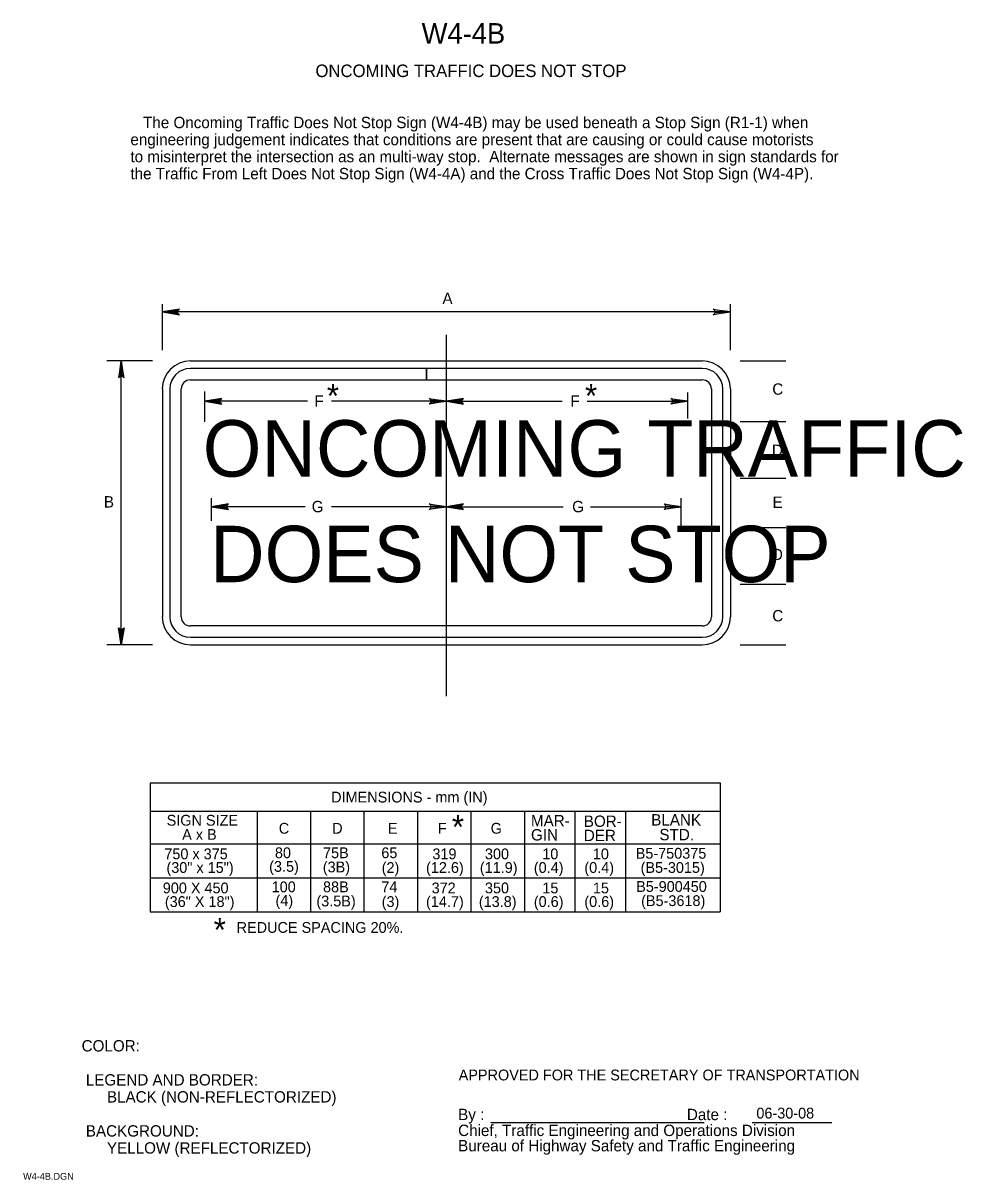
# Model space of a CAD drawing. Extents: x 0.013 to 0.219, y 0.004 to 0.259.
import ezdxf

# ---------------------------------------------------------------- set-up
doc = ezdxf.new("R2010")
doc.units = 0
for name, color, linetype in [('1', 7, 'Continuous'), ('2', 7, 'Continuous'), ('3', 7, 'Continuous')]:
    doc.layers.add(name, color=color, linetype=linetype)

# ---------------------------------------------------------------- blocks, each defined once
blk = doc.blocks.new('RARROW')
at = {"layer": '3'}
for p, q in [((-2.156, 0.285), (-2.2665, 0.384625)), ((-2.2665, 0.384625), (0, 0)), ((0, 0), (-2.2665, -0.379125)), ((-2.156, 0.285), (-2.075625, 0.12075)), ((0, 0), (-2.156, 0.285)), ((-2.14975, -0.2705), (0, 0)), ((-2.075625, 0.12075), (0, 0)), ((0, 0), (-2.074, -0.108)), ((-2.2665, -0.379125), (-2.14975, -0.2705)), ((-2.074, -0.108), (-2.14975, -0.2705))]:
    blk.add_line(p, q, dxfattribs=at)

msp = doc.modelspace()

# ---------------------------------------------------------------- linework, layer by layer
at = {"layer": '1'}
for p, q in [((0.10565, 0.11086), (0.10565, 0.19039)), ((0.0341, 0.12213), (0.0341, 0.18463)), ((0.10127, 0.18297), (0.04931, 0.18297)), ((0.10127, 0.18047), (0.10127, 0.18297)), ((0.16198, 0.18297), (0.10127, 0.18297)), ((0.10127, 0.18297), (0.10127, 0.18047)), ((0.04481, 0.17847), (0.04481, 0.1283)), ((0.04731, 0.1283), (0.04731, 0.17847)), ((0.04931, 0.18047), (0.10127, 0.18047)), ((0.10127, 0.18047), (0.16198, 0.18047)), ((0.16398, 0.17847), (0.16398, 0.1283)), ((0.16648, 0.1283), (0.16648, 0.17847)), ((0.05248, 0.17123), (0.05248, 0.17793)), ((0.10565, 0.17326), (0.10565, 0.17793)), ((0.15881, 0.17194), (0.15881, 0.17769)), ((0.05398, 0.14943), (0.05398, 0.15446)), ((0.10565, 0.15098), (0.10565, 0.1541)), ((0.15731, 0.14823), (0.15731, 0.15446)), ((0.16198, 0.1263), (0.04931, 0.1263)), ((0.04931, 0.1238), (0.16198, 0.1238)), ((0.11544, 0.01695), (0.16242, 0.01695)), ((0.17295, 0.01695), (0.1905, 0.01695))]:
    msp.add_line(p, q, dxfattribs=at)
for centre, radius, start, end in [((0.04931, 0.17847), 0.00617, 90, 180), ((0.16198, 0.17847), 0.00617, 360, 90), ((0.04931, 0.17847), 0.0045, 90, 180), ((0.16198, 0.17847), 0.0045, 0, 90), ((0.04931, 0.17847), 0.002, 90, 180), ((0.16198, 0.17847), 0.002, 0, 90), ((0.04931, 0.1283), 0.00617, 180, 270), ((0.04931, 0.1283), 0.0045, 180, 270), ((0.04931, 0.1283), 0.002, 180, 270), ((0.16198, 0.1283), 0.00617, 270, 0), ((0.16198, 0.1283), 0.0045, 270, 0), ((0.16198, 0.1283), 0.002, 270, 0)]:
    msp.add_arc(centre, radius, start, end, dxfattribs=at)
at = {"layer": '3'}
for p, q in [((0.04315, 0.18704), (0.04315, 0.1971)), ((0.16815, 0.18704), (0.16815, 0.1971)), ((0.16815, 0.19541), (0.04315, 0.19541)), ((0.04098, 0.18463), (0.03092, 0.18463)), ((0.04931, 0.18463), (0.16198, 0.18463)), ((0.17031, 0.18463), (0.18037, 0.18463)), ((0.04315, 0.17847), (0.04315, 0.1283)), ((0.16815, 0.17847), (0.16815, 0.1283)), ((0.07509, 0.17577), (0.05248, 0.17577)), ((0.10565, 0.17577), (0.08036, 0.17577)), ((0.10565, 0.17577), (0.13114, 0.17577)), ((0.13665, 0.17577), (0.15881, 0.17577)), ((0.17031, 0.1713), (0.18037, 0.1713)), ((0.17031, 0.1588), (0.18037, 0.1588)), ((0.07461, 0.15254), (0.05398, 0.15254)), ((0.10565, 0.15254), (0.08036, 0.15254)), ((0.10565, 0.15254), (0.13138, 0.15254)), ((0.13737, 0.15254), (0.15731, 0.15254)), ((0.17031, 0.14796), (0.18037, 0.14796)), ((0.17031, 0.13546), (0.18037, 0.13546)), ((0.04098, 0.12213), (0.03092, 0.12213)), ((0.04931, 0.12213), (0.16198, 0.12213)), ((0.17031, 0.12213), (0.18037, 0.12213)), ((0.04046, 0.09173), (0.16589, 0.09173)), ((0.04046, 0.09168), (0.04046, 0.06336)), ((0.16589, 0.09173), (0.16589, 0.06336)), ((0.16589, 0.08548), (0.04046, 0.08548)), ((0.06402, 0.08548), (0.06402, 0.06336)), ((0.07577, 0.08543), (0.07577, 0.06336)), ((0.08752, 0.08543), (0.08752, 0.06336)), ((0.09927, 0.08543), (0.09927, 0.06336)), ((0.11102, 0.08543), (0.11102, 0.06336)), ((0.12284, 0.08548), (0.12284, 0.06336)), ((0.13396, 0.08548), (0.13396, 0.06336)), ((0.14509, 0.08548), (0.14509, 0.06336)), ((0.04046, 0.07836), (0.16589, 0.07836)), ((0.04046, 0.07086), (0.16589, 0.07086)), ((0.04046, 0.06336), (0.16589, 0.06336))]:
    msp.add_line(p, q, dxfattribs=at)

# ---------------------------------------------------------------- block references
at = {"layer": '3', "xscale": 0.0016545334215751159}
for p, yscale, rotation in [((0.04315, 0.19541), -0.0016366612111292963, -180), ((0.0341, 0.18463), -0.0016366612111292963, 90), ((0.05248, 0.17577), -0.0016366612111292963, -180), ((0.10565, 0.17577), -0.0016366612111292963, -180), ((0.05398, 0.15254), -0.0016366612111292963, -180), ((0.10565, 0.15254), -0.0016366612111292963, -180), ((0.0341, 0.12213), 0.0016366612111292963, -90)]:
    msp.add_blockref('RARROW', p, dxfattribs=dict(at, yscale=yscale, rotation=rotation))
at = {"layer": '3', "xscale": 0.0016545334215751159, "yscale": 0.0016366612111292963}
for p in [(0.16815, 0.19541), (0.10565, 0.17577), (0.15881, 0.17577), (0.10565, 0.15254), (0.15731, 0.15254)]:
    msp.add_blockref('RARROW', p, dxfattribs=at)

# ---------------------------------------------------------------- texts
at = {"layer": '1'}
for s, height, p in [('W4-4B', 0.0045, (0.10021, 0.2545)), ('ONCOMING TRAFFIC DOES NOT STOP', 0.0027503, (0.07684, 0.24713)), ('COLOR:', 0.0025, (0.02538, 0.03262)), ('APPROVED FOR THE SECRETARY OF TRANSPORTATION', 0.0023752, (0.10837, 0.02625)), (' LEGEND AND BORDER:', 0.0024998, (0.02538, 0.02512)), ('      BLACK (NON-REFLECTORIZED)', 0.0024998, (0.02538, 0.02138)), ('By :                                                Date :', 0.0024998, (0.10825, 0.0175)), (' BACKGROUND:', 0.0024998, (0.02538, 0.01388)), ('Chief, Traffic Engineering and Operations Division', 0.0024998, (0.10825, 0.014)), ('      YELLOW (REFLECTORIZED)', 0.0024998, (0.02538, 0.01013)), ('Bureau of Highway Safety and Traffic Engineering', 0.0024998, (0.10825, 0.01063)), ('W4-4B.DGN', 0.0015, (0.0125, 0.00438))]:
    msp.add_text(s, height=height, dxfattribs=at).set_placement(p)
at = {"layer": '2'}
for s, height, p in [('   The Oncoming Traffic Does Not Stop Sign (W4-4B) may be used beneath a Stop Sign (R1-1) when', 0.0024998, (0.03612, 0.23588)), ('engineering judgement indicates that conditions are present that are causing or could cause motorists', 0.00249975, (0.03612, 0.23213)), ('to misinterpret the intersection as an multi-way stop.  Alternate messages are shown in sign standards for', 0.00249975, (0.03612, 0.22838)), ('the Traffic From Left Does Not Stop Sign (W4-4A) and the Cross Traffic Does Not Stop Sign (W4-4P).', 0.0024998, (0.03612, 0.22463))]:
    msp.add_text(s, height=height, dxfattribs=at).set_placement(p)
at = {"layer": '3'}
for s, height, p in [('A', 0.0025, (0.10479, 0.19716)), ('*', 0.00518, (0.13616, 0.17437)), ('C', 0.0025, (0.17738, 0.1772)), ('F', 0.0025, (0.13297, 0.17456)), ('ONCOMING TRAFFIC', 0.01242, (0.05204, 0.15917)), ('B', 0.0025, (0.03028, 0.15237)), ('G', 0.0025, (0.13334, 0.15132)), ('DOES NOT STOP', 0.01242, (0.05365, 0.13593)), ('DIMENSIONS - mm (IN)', 0.0023752, (0.0803, 0.08743)), ('SIGN SIZE', 0.002375, (0.04409, 0.08233)), ('MAR-', 0.0025, (0.12427, 0.08218)), ('BOR-', 0.0025, (0.1359, 0.08206)), ('BLANK', 0.0025, (0.15074, 0.08236)), ('A x B', 0.002375, (0.04751, 0.07921)), ('C', 0.00238, (0.06877, 0.08056)), ('D', 0.00238, (0.08052, 0.08056)), ('E', 0.00238, (0.09277, 0.08056)), ('F', 0.00238, (0.10377, 0.08056)), ('G', 0.00238, (0.1154, 0.08056)), ('GIN', 0.0025, (0.12427, 0.07906)), ('STD.', 0.0025, (0.15254, 0.07911)), ('DER', 0.0025, (0.1359, 0.07893)), ('750 x 375', 0.002375, (0.04359, 0.07493)), ('80', 0.002375, (0.06792, 0.07517)), ('75B', 0.002375, (0.07851, 0.07517)), ('65', 0.002375, (0.09134, 0.07517)), ('319', 0.002375, (0.10258, 0.07493)), ('300', 0.002375, (0.11414, 0.07493)), ('10', 0.002375, (0.12676, 0.07493)), ('10', 0.002375, (0.13789, 0.07493)), ('B5-750375', 0.002375, (0.14732, 0.07506)), ('(30" x 15")', 0.0023752, (0.04405, 0.07193)), ('(3.5)', 0.002375, (0.06665, 0.07217)), ('(3B)', 0.002375, (0.07846, 0.07205)), ('(2)', 0.002375, (0.09142, 0.07192)), ('(12.6)', 0.002375, (0.10118, 0.07193)), ('(11.9)', 0.002375, (0.11302, 0.07193)), ('(0.4)', 0.002375, (0.1249, 0.07193)), ('(0.4)', 0.002375, (0.13602, 0.07193)), ('(B5-3015)', 0.002375, (0.1484, 0.07193)), ('900 X 450', 0.002375, (0.04324, 0.06743)), ('100', 0.002375, (0.0672, 0.06767)), ('88B', 0.002375, (0.07851, 0.06767)), ('74', 0.002375, (0.09133, 0.06767)), ('372', 0.002375, (0.10241, 0.06743)), ('350', 0.002375, (0.11414, 0.06743)), ('15', 0.002375, (0.12677, 0.06743)), ('15', 0.002375, (0.1379, 0.06743)), ('B5-900450', 0.002375, (0.14743, 0.06775)), ('(36" X 18")', 0.0023752, (0.0437, 0.06443)), ('(4)', 0.002375, (0.06805, 0.06467)), ('(3.5B)', 0.002375, (0.07705, 0.06455)), ('(3)', 0.002375, (0.09142, 0.06442)), ('(14.7)', 0.002375, (0.10118, 0.06443)), ('(13.8)', 0.002375, (0.1128, 0.06443)), ('(0.6)', 0.002375, (0.1249, 0.06443)), ('(0.6)', 0.002375, (0.13602, 0.06443)), ('(B5-3618)', 0.002375, (0.14852, 0.06463)), ('REDUCE SPACING 20%.', 0.0023752, (0.05949, 0.05873)), ('06-30-08', 0.002375, (0.17388, 0.01786))]:
    msp.add_text(s, height=height, dxfattribs=at).set_placement(p)
for s, height, p in [('*', 0.00518, (0.07934, 0.17437)), ('F', 0.0025, (0.07661, 0.17456)), ('D', 0.0025, (0.1773, 0.16372)), ('G', 0.0025, (0.07602, 0.15132)), ('E', 0.0025, (0.17744, 0.15228)), ('D', 0.0025, (0.1773, 0.14078)), ('C', 0.0025, (0.17738, 0.1273)), ('*', 0.00518, (0.10685, 0.07946)), ('*', 0.00518, (0.05444, 0.05682))]:
    msp.add_text(s, height=height, rotation=360, dxfattribs=at).set_placement(p)

doc.saveas('drawing.dxf')
